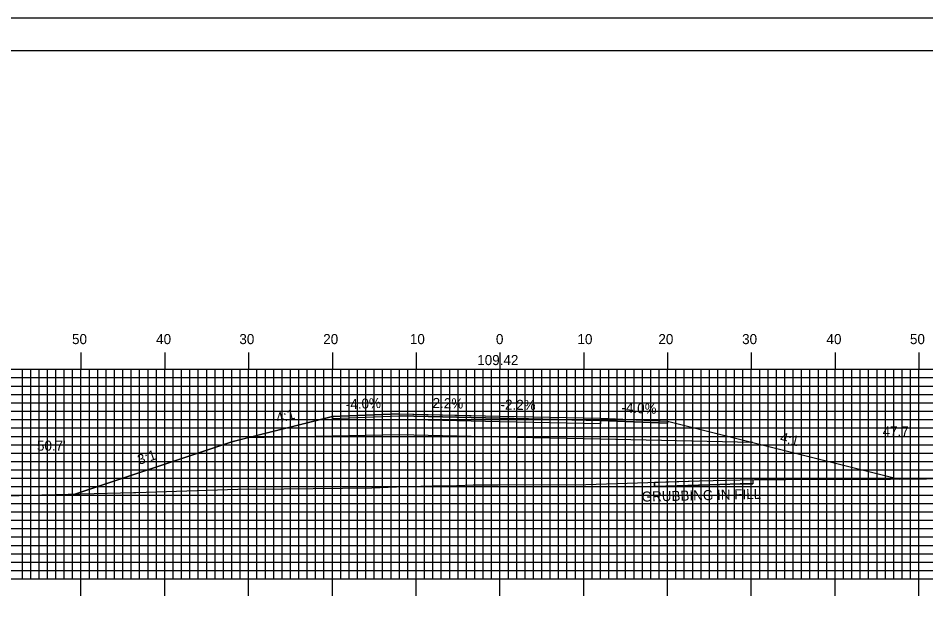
# Model space of a CAD drawing. Extents: x 1765333 to 1765676, y 442591 to 442811.
# Drawn here: x 1765440.9 to 1765549.2, y 442741.2 to 442810.5 of the extents above; entities that cross this region are included whole.
import ezdxf

# ---------------------------------------------------------------- set-up
doc = ezdxf.new("R2010")
doc.units = 0
for name, color, linetype in [('ANNOTATION', 7, 'Continuous'), ('BORDER', 7, 'Continuous'), ('D_Roadway_Centerline', 7, 'Continuous'), ('D_Roadway_Centerline_Text', 7, 'Continuous'), ('D_Roadway_Edge_Shoulder', 7, 'Continuous'), ('D_Roadway_Edge_TW', 7, 'Continuous'), ('D_Roadway_Pavement', 7, 'Continuous'), ('D_Roadway_SlopeLines', 7, 'Continuous'), ('D_Roadway_SubGrade', 7, 'Continuous'), ('D_Text_Standard', 7, 'Continuous'), ('GRUBBING IN FILL', 7, 'Continuous'), ('H_V ANNOTATION', 7, 'Continuous'), ('MAJOR', 7, 'Continuous'), ('MINOR', 7, 'Continuous'), ('PLOT BOUNDARY', 7, 'Continuous'), ('S_Roadway_Centerline', 7, 'Continuous')]:
    doc.layers.add(name, color=color, linetype=linetype)

msp = doc.modelspace()

# ---------------------------------------------------------------- linework, layer by layer
at = {"layer": 'BORDER'}
msp.add_lwpolyline([(1765348.77, 442596.67), (1765668.77, 442596.67), (1765668.77, 442806.67), (1765348.77, 442806.67)], close=True, dxfattribs=at)
at = {"layer": 'D_Roadway_Centerline'}
msp.add_lwpolyline([(1765447.63, 442753.78), (1765466.37, 442760.02), (1765466.37, 442760.03), (1765468.2, 442760.48), (1765478.37, 442763.02), (1765478.37, 442763.03), (1765478.37, 442763.03), (1765486.37, 442763.35), (1765491.18, 442763.24), (1765498.37, 442763.08), (1765510.37, 442762.82), (1765511.76, 442762.76), (1765518.37, 442762.5), (1765518.37, 442762.5), (1765518.37, 442762.5), (1765528.55, 442759.95), (1765546.04, 442755.58), (1765546.04, 442755.58)], dxfattribs=at)
at = {"layer": 'D_Roadway_Edge_Shoulder'}
for points in [[(1765486.37, 442763.35), (1765478.37, 442763.03), (1765478.37, 442762.78), (1765486.37, 442763.1)], [(1765510.37, 442762.82), (1765518.37, 442762.5), (1765518.37, 442762.25), (1765510.37, 442762.57)]]:
    msp.add_lwpolyline(points, close=True, dxfattribs=at)
at = {"layer": 'D_Roadway_Edge_TW'}
msp.add_lwpolyline([(1765486.37, 442763.1), (1765486.37, 442763.35), (1765498.37, 442763.08), (1765510.37, 442762.82), (1765510.37, 442762.57), (1765498.37, 442762.83)], close=True, dxfattribs=at)
at = {"layer": 'D_Roadway_Pavement'}
msp.add_lwpolyline([(1765486.37, 442762.68), (1765486.37, 442763.1), (1765498.37, 442762.83), (1765510.37, 442762.57), (1765510.37, 442762.15), (1765498.37, 442762.41)], close=True, dxfattribs=at)
at = {"layer": 'D_Roadway_SlopeLines'}
for points in [[(1765478.37, 442763.03), (1765466.37, 442760.03), (1765447.63, 442753.78)], [(1765518.37, 442762.5), (1765528.55, 442759.95), (1765546.04, 442755.58)]]:
    msp.add_lwpolyline(points, dxfattribs=at)
at = {"layer": 'D_Roadway_SubGrade'}
msp.add_lwpolyline([(1765486.37, 442760.85), (1765468.2, 442760.48), (1765478.37, 442763.03), (1765478.37, 442762.78), (1765486.37, 442763.1), (1765498.37, 442762.83), (1765510.37, 442762.57), (1765518.37, 442762.25), (1765518.37, 442762.5), (1765528.55, 442759.95), (1765510.37, 442760.32), (1765498.37, 442760.58)], close=True, dxfattribs=at)
at = {"layer": 'GRUBBING IN FILL'}
for p, q in [((1765516.83, 442755.19), (1765516.83, 442754.69)), ((1765516.83, 442755.19), (1765516.83, 442754.69)), ((1765528.55, 442755.52), (1765528.55, 442755.02)), ((1765528.55, 442755.52), (1765528.55, 442755.02))]:
    msp.add_line(p, q, dxfattribs=at)
msp.add_lwpolyline([(1765516.83, 442755.19), (1765522.17, 442755.36), (1765527.04, 442755.49), (1765528.55, 442755.52), (1765528.55, 442755.02), (1765527.05, 442754.99), (1765524.62, 442754.92), (1765519.51, 442754.77), (1765516.83, 442754.69)], close=True, dxfattribs=at)
msp.add_lwpolyline([(1765516.83, 442755.19), (1765522.17, 442755.36), (1765527.04, 442755.49), (1765528.55, 442755.52), (1765528.55, 442755.02), (1765527.05, 442754.99), (1765524.62, 442754.92), (1765519.51, 442754.77), (1765516.83, 442754.69)], close=True, dxfattribs=at)
msp.add_lwpolyline([(1765516.83, 442754.69), (1765522.18, 442754.86), (1765527.05, 442754.99), (1765528.55, 442755.02)], dxfattribs=at)
msp.add_lwpolyline([(1765516.83, 442754.69), (1765522.18, 442754.86), (1765527.05, 442754.99), (1765528.55, 442755.02)], dxfattribs=at)
at = {"layer": 'MAJOR'}
for p, q in [((1765448.37, 442770.67), (1765448.37, 442768.67)), ((1765458.37, 442770.67), (1765458.37, 442768.67)), ((1765468.37, 442770.67), (1765468.37, 442768.67)), ((1765478.37, 442770.67), (1765478.37, 442768.67)), ((1765488.37, 442770.67), (1765488.37, 442768.67)), ((1765498.37, 442770.67), (1765498.37, 442768.67)), ((1765508.37, 442770.67), (1765508.37, 442768.67)), ((1765518.37, 442770.67), (1765518.37, 442768.67)), ((1765528.37, 442770.67), (1765528.37, 442768.67)), ((1765538.37, 442770.67), (1765538.37, 442768.67)), ((1765548.37, 442770.67), (1765548.37, 442768.67)), ((1765358.37, 442768.67), (1765638.37, 442768.67)), ((1765358.37, 442768.67), (1765638.37, 442768.67)), ((1765448.37, 442743.67), (1765448.37, 442768.67)), ((1765458.37, 442743.67), (1765458.37, 442768.67)), ((1765468.37, 442743.67), (1765468.37, 442768.67)), ((1765478.37, 442743.67), (1765478.37, 442768.67)), ((1765488.37, 442743.67), (1765488.37, 442768.67)), ((1765498.37, 442743.67), (1765498.37, 442768.67)), ((1765508.37, 442743.67), (1765508.37, 442768.67)), ((1765518.37, 442743.67), (1765518.37, 442768.67)), ((1765528.37, 442743.67), (1765528.37, 442768.67)), ((1765538.37, 442743.67), (1765538.37, 442768.67)), ((1765548.37, 442743.67), (1765548.37, 442768.67)), ((1765358.37, 442763.67), (1765638.37, 442763.67)), ((1765358.37, 442758.67), (1765638.37, 442758.67)), ((1765358.37, 442753.67), (1765638.37, 442753.67)), ((1765358.37, 442748.67), (1765638.37, 442748.67)), ((1765358.37, 442743.67), (1765638.37, 442743.67)), ((1765358.37, 442743.67), (1765638.37, 442743.67)), ((1765448.37, 442741.66), (1765448.37, 442743.67)), ((1765458.37, 442741.66), (1765458.37, 442743.67)), ((1765468.37, 442741.66), (1765468.37, 442743.67)), ((1765478.37, 442741.66), (1765478.37, 442743.67)), ((1765488.37, 442741.66), (1765488.37, 442743.67)), ((1765498.37, 442741.66), (1765498.37, 442743.67)), ((1765508.37, 442741.66), (1765508.37, 442743.67)), ((1765518.37, 442741.66), (1765518.37, 442743.67)), ((1765528.37, 442741.66), (1765528.37, 442743.67)), ((1765538.37, 442741.66), (1765538.37, 442743.67)), ((1765548.37, 442741.66), (1765548.37, 442743.67))]:
    msp.add_line(p, q, dxfattribs=at)
at = {"layer": 'MINOR'}
for p, q in [((1765441.37, 442743.67), (1765441.37, 442768.67)), ((1765442.37, 442743.67), (1765442.37, 442768.67)), ((1765443.37, 442743.67), (1765443.37, 442768.67)), ((1765444.37, 442743.67), (1765444.37, 442768.67)), ((1765445.37, 442743.67), (1765445.37, 442768.67)), ((1765446.37, 442743.67), (1765446.37, 442768.67)), ((1765447.37, 442743.67), (1765447.37, 442768.67)), ((1765449.37, 442743.67), (1765449.37, 442768.67)), ((1765450.37, 442743.67), (1765450.37, 442768.67)), ((1765451.37, 442743.67), (1765451.37, 442768.67)), ((1765452.37, 442743.67), (1765452.37, 442768.67)), ((1765453.37, 442743.67), (1765453.37, 442768.67)), ((1765454.37, 442743.67), (1765454.37, 442768.67)), ((1765455.37, 442743.67), (1765455.37, 442768.67)), ((1765456.37, 442743.67), (1765456.37, 442768.67)), ((1765457.37, 442743.67), (1765457.37, 442768.67)), ((1765459.37, 442743.67), (1765459.37, 442768.67)), ((1765460.37, 442743.67), (1765460.37, 442768.67)), ((1765461.37, 442743.67), (1765461.37, 442768.67)), ((1765462.37, 442743.67), (1765462.37, 442768.67)), ((1765463.37, 442743.67), (1765463.37, 442768.67)), ((1765464.37, 442743.67), (1765464.37, 442768.67)), ((1765465.37, 442743.67), (1765465.37, 442768.67)), ((1765466.37, 442743.67), (1765466.37, 442768.67)), ((1765467.37, 442743.67), (1765467.37, 442768.67)), ((1765469.37, 442743.67), (1765469.37, 442768.67)), ((1765470.37, 442743.67), (1765470.37, 442768.67)), ((1765471.37, 442743.67), (1765471.37, 442768.67)), ((1765472.37, 442743.67), (1765472.37, 442768.67)), ((1765473.37, 442743.67), (1765473.37, 442768.67)), ((1765474.37, 442743.67), (1765474.37, 442768.67)), ((1765475.37, 442743.67), (1765475.37, 442768.67)), ((1765476.37, 442743.67), (1765476.37, 442768.67)), ((1765477.37, 442743.67), (1765477.37, 442768.67)), ((1765479.37, 442743.67), (1765479.37, 442768.67)), ((1765480.37, 442743.67), (1765480.37, 442768.67)), ((1765481.37, 442743.67), (1765481.37, 442768.67)), ((1765482.37, 442743.67), (1765482.37, 442768.67)), ((1765483.37, 442743.67), (1765483.37, 442768.67)), ((1765484.37, 442743.67), (1765484.37, 442768.67)), ((1765485.37, 442743.67), (1765485.37, 442768.67)), ((1765486.37, 442743.67), (1765486.37, 442768.67)), ((1765487.37, 442743.67), (1765487.37, 442768.67)), ((1765489.37, 442743.67), (1765489.37, 442768.67)), ((1765490.37, 442743.67), (1765490.37, 442768.67)), ((1765491.37, 442743.67), (1765491.37, 442768.67)), ((1765492.37, 442743.67), (1765492.37, 442768.67)), ((1765493.37, 442743.67), (1765493.37, 442768.67)), ((1765494.37, 442743.67), (1765494.37, 442768.67)), ((1765495.37, 442743.67), (1765495.37, 442768.67)), ((1765496.37, 442743.67), (1765496.37, 442768.67)), ((1765497.37, 442743.67), (1765497.37, 442768.67)), ((1765499.37, 442743.67), (1765499.37, 442768.67)), ((1765500.37, 442743.67), (1765500.37, 442768.67)), ((1765501.37, 442743.67), (1765501.37, 442768.67)), ((1765502.37, 442743.67), (1765502.37, 442768.67)), ((1765503.37, 442743.67), (1765503.37, 442768.67)), ((1765504.37, 442743.67), (1765504.37, 442768.67)), ((1765505.37, 442743.67), (1765505.37, 442768.67)), ((1765506.37, 442743.67), (1765506.37, 442768.67)), ((1765507.37, 442743.67), (1765507.37, 442768.67)), ((1765509.37, 442743.67), (1765509.37, 442768.67)), ((1765510.37, 442743.67), (1765510.37, 442768.67)), ((1765511.37, 442743.67), (1765511.37, 442768.67)), ((1765512.37, 442743.67), (1765512.37, 442768.67)), ((1765513.37, 442743.67), (1765513.37, 442768.67)), ((1765514.37, 442743.67), (1765514.37, 442768.67)), ((1765515.37, 442743.67), (1765515.37, 442768.67)), ((1765516.37, 442743.67), (1765516.37, 442768.67)), ((1765517.37, 442743.67), (1765517.37, 442768.67)), ((1765519.37, 442743.67), (1765519.37, 442768.67)), ((1765520.37, 442743.67), (1765520.37, 442768.67)), ((1765521.37, 442743.67), (1765521.37, 442768.67)), ((1765522.37, 442743.67), (1765522.37, 442768.67)), ((1765523.37, 442743.67), (1765523.37, 442768.67)), ((1765524.37, 442743.67), (1765524.37, 442768.67)), ((1765525.37, 442743.67), (1765525.37, 442768.67)), ((1765526.37, 442743.67), (1765526.37, 442768.67)), ((1765527.37, 442743.67), (1765527.37, 442768.67)), ((1765529.37, 442743.67), (1765529.37, 442768.67)), ((1765530.37, 442743.67), (1765530.37, 442768.67)), ((1765531.37, 442743.67), (1765531.37, 442768.67)), ((1765532.37, 442743.67), (1765532.37, 442768.67)), ((1765533.37, 442743.67), (1765533.37, 442768.67)), ((1765534.37, 442743.67), (1765534.37, 442768.67)), ((1765535.37, 442743.67), (1765535.37, 442768.67)), ((1765536.37, 442743.67), (1765536.37, 442768.67)), ((1765537.37, 442743.67), (1765537.37, 442768.67)), ((1765539.37, 442743.67), (1765539.37, 442768.67)), ((1765540.37, 442743.67), (1765540.37, 442768.67)), ((1765541.37, 442743.67), (1765541.37, 442768.67)), ((1765542.37, 442743.67), (1765542.37, 442768.67)), ((1765543.37, 442743.67), (1765543.37, 442768.67)), ((1765544.37, 442743.67), (1765544.37, 442768.67)), ((1765545.37, 442743.67), (1765545.37, 442768.67)), ((1765546.37, 442743.67), (1765546.37, 442768.67)), ((1765547.37, 442743.67), (1765547.37, 442768.67)), ((1765358.37, 442767.67), (1765638.37, 442767.67)), ((1765358.37, 442766.67), (1765638.37, 442766.67)), ((1765358.37, 442765.67), (1765638.37, 442765.67)), ((1765358.37, 442764.67), (1765638.37, 442764.67)), ((1765358.37, 442762.67), (1765638.37, 442762.67)), ((1765358.37, 442761.67), (1765638.37, 442761.67)), ((1765358.37, 442760.67), (1765638.37, 442760.67)), ((1765358.37, 442759.67), (1765638.37, 442759.67)), ((1765358.37, 442757.67), (1765638.37, 442757.67)), ((1765358.37, 442756.67), (1765638.37, 442756.67)), ((1765358.37, 442755.67), (1765638.37, 442755.67)), ((1765358.37, 442754.67), (1765638.37, 442754.67)), ((1765358.37, 442752.67), (1765638.37, 442752.67)), ((1765358.37, 442751.67), (1765638.37, 442751.67)), ((1765358.37, 442750.67), (1765638.37, 442750.67)), ((1765358.37, 442749.67), (1765638.37, 442749.67)), ((1765358.37, 442747.67), (1765638.37, 442747.67)), ((1765358.37, 442746.67), (1765638.37, 442746.67)), ((1765358.37, 442745.67), (1765638.37, 442745.67)), ((1765358.37, 442744.67), (1765638.37, 442744.67))]:
    msp.add_line(p, q, dxfattribs=at)
at = {"layer": 'PLOT BOUNDARY'}
msp.add_lwpolyline([(1765332.58, 442590.55), (1765672.58, 442590.55), (1765672.58, 442810.55), (1765332.58, 442810.55)], close=True, dxfattribs=at)
at = {"layer": 'S_Roadway_Centerline'}
msp.add_lwpolyline([(1765436.37, 442753.47), (1765442.13, 442753.64), (1765454.65, 442753.96), (1765454.73, 442753.96), (1765454.9, 442753.97), (1765467.07, 442754.38), (1765472.56, 442754.4), (1765483.09, 442754.54), (1765486.03, 442754.63), (1765490.41, 442754.75), (1765493.21, 442754.82), (1765495.18, 442754.87), (1765498.16, 442754.89), (1765508.63, 442754.93), (1765522.17, 442755.36), (1765527.04, 442755.49), (1765528.75, 442755.52), (1765532.48, 442755.53), (1765544.97, 442755.57), (1765553.57, 442755.65)], dxfattribs=at)

# ---------------------------------------------------------------- texts
at = {"layer": 'ANNOTATION'}
for s, rotation, p in [('-4.0%', 2.2909, (1765480, 442763.89)), ('2.2%', 358.7397, (1765490.32, 442764.06)), ('-2.2%', 358.7397, (1765498.43, 442763.88)), ('-4.0%', 357.7094, (1765512.85, 442763.52)), ('4:1', 14.0384, (1765471.82, 442762.25)), ('4:1', 345.9636, (1765531.71, 442760.02)), ('3:1', 18.4355, (1765455.34, 442757.26))]:
    msp.add_text(s, height=1.2, rotation=rotation, dxfattribs=at).set_placement(p)
at = {"layer": 'D_Roadway_Centerline'}
for s, p in [('C', (1765498.37, 442763.08)), ('L', (1765498.37, 442763.07))]:
    msp.add_text(s, height=0.0146, dxfattribs=at).set_placement(p)
at = {"layer": 'D_Roadway_Centerline_Text'}
msp.add_text('109.42', height=1.2, dxfattribs=at).set_placement((1765495.66, 442769.17))
at = {"layer": 'D_Text_Standard'}
for s, p in [("47.7'", (1765544.04, 442760.67)), ("50.7'", (1765443.12, 442758.96))]:
    msp.add_text(s, height=1.2, dxfattribs=at).set_placement(p)
at = {"layer": 'GRUBBING IN FILL'}
msp.add_text('GRUBBING IN FILL', height=1.2, rotation=1.3478, dxfattribs=at).set_placement((1765515.29, 442752.88))
at = {"layer": 'H_V ANNOTATION'}
for s, p in [('50', (1765447.3, 442771.67)), ('40', (1765457.34, 442771.67)), ('30', (1765467.27, 442771.67)), ('20', (1765477.28, 442771.67)), ('10', (1765487.62, 442771.67)), ('0', (1765497.89, 442771.67)), ('10', (1765507.62, 442771.67)), ('20', (1765517.28, 442771.67)), ('30', (1765527.27, 442771.67)), ('40', (1765537.34, 442771.67)), ('50', (1765547.3, 442771.67))]:
    msp.add_text(s, height=1.2, dxfattribs=at).set_placement(p)

doc.saveas('drawing.dxf')
